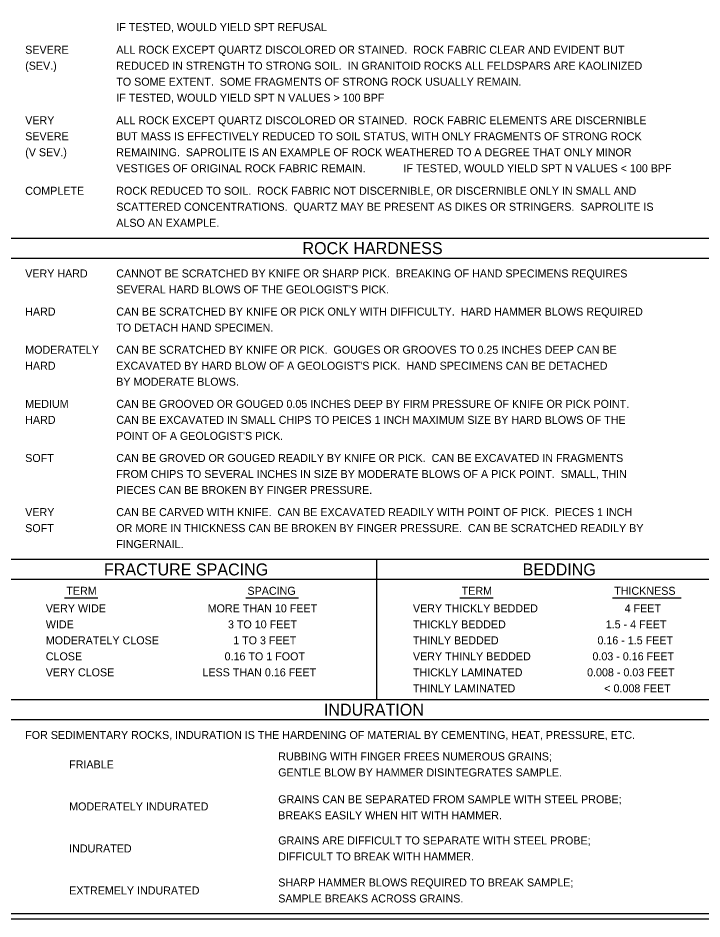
# Model space of a CAD drawing. Extents: x 265553 to 275568, y 168312 to 173522.
# Drawn here: x 267674.3 to 268044.8, y 170247.1 to 170735.3 of the extents above; entities that cross this region are included whole.
import ezdxf

# ---------------------------------------------------------------- set-up
doc = ezdxf.new("R2010")
doc.units = 0
doc.layers.add('Geotech Sheets and Borders Cell', color=7, linetype='Continuous')
doc.layers.add('Sheet Plot Border Inside CELL', color=7, linetype='Continuous')

msp = doc.modelspace()

# ---------------------------------------------------------------- linework, layer by layer
at = {"layer": 'Geotech Sheets and Borders Cell'}
for p, q in [((267670.42, 170616.07), (268066.96, 170616.07)), ((267670.42, 170605.22), (268066.96, 170605.22)), ((268420.42, 170441.94), (267670.42, 170441.94)), ((267868.69, 170365.94), (267868.69, 170441.94)), ((268066.96, 170431.1), (267670.42, 170431.1)), ((267699.57, 170421.19), (267717.57, 170421.19)), ((267797.7, 170421.19), (267826.25, 170421.19)), ((267913.75, 170421.19), (267931.75, 170421.19)), ((267996.37, 170421.19), (268033.61, 170421.19)), ((268066.96, 170365.94), (267670.42, 170365.94)), ((268066.96, 170355.1), (267670.42, 170355.1))]:
    msp.add_line(p, q, dxfattribs=at)
msp.add_lwpolyline([(266920.42, 171299.94), (268420.42, 171299.94), (268420.42, 170249.94), (266920.42, 170249.94)], close=True, dxfattribs=at)
at = {"layer": 'Sheet Plot Border Inside CELL'}
msp.add_lwpolyline([(266765.25, 170247.11), (268432.92, 170247.11), (268432.92, 171302.77), (266765.25, 171302.77)], close=True, dxfattribs=at)

# ---------------------------------------------------------------- texts
at = {"layer": 'Geotech Sheets and Borders Cell'}
for s, height, p in [('IF TESTED, WOULD YIELD SPT REFUSAL', 4.3381, (267727.56, 170728.22)), ('SEVERE', 4.338, (267678.23, 170715.99)), ('ALL ROCK EXCEPT QUARTZ DISCOLORED OR STAINED.  ROCK FABRIC CLEAR AND EVIDENT BUT ', 4.3381, (267727.56, 170715.99)), ('(SEV.)', 4.338, (267678.23, 170707.32)), ('REDUCED IN STRENGTH TO STRONG SOIL.  IN GRANITOID ROCKS ALL FELDSPARS ARE KAOLINIZED', 4.3381, (267727.56, 170707.32)), ('TO SOME EXTENT.  SOME FRAGMENTS OF STRONG ROCK USUALLY REMAIN.', 4.3381, (267727.56, 170698.65)), ('IF TESTED, WOULD YIELD SPT N VALUES > 100 BPF', 4.3381, (267727.56, 170689.99)), ('VERY', 4.338, (267678.23, 170677.77)), ('ALL ROCK EXCEPT QUARTZ DISCOLORED OR STAINED.  ROCK FABRIC ELEMENTS ARE DISCERNIBLE ', 4.3381, (267727.56, 170677.77)), ('SEVERE', 4.338, (267678.23, 170669.1)), ('BUT MASS IS EFFECTIVELY REDUCED TO SOIL STATUS, WITH ONLY FRAGMENTS OF STRONG ROCK ', 4.3381, (267727.56, 170669.1)), ('(V SEV.)', 4.338, (267678.23, 170660.43)), ('REMAINING.  SAPROLITE IS AN EXAMPLE OF ROCK WEATHERED TO A DEGREE THAT ONLY MINOR ', 4.3381, (267727.56, 170660.43)), ('VESTIGES OF ORIGINAL ROCK FABRIC REMAIN.   ', 4.3381, (267727.56, 170651.76)), ('IF TESTED, WOULD YIELD SPT N VALUES < 100 BPF', 4.3381, (267883.16, 170651.76)), ('COMPLETE', 4.338, (267678.23, 170639.55)), ('ROCK REDUCED TO SOIL.  ROCK FABRIC NOT DISCERNIBLE, OR DISCERNIBLE ONLY IN SMALL AND ', 4.3381, (267727.56, 170639.55)), ('SCATTERED CONCENTRATIONS.  QUARTZ MAY BE PRESENT AS DIKES OR STRINGERS.  SAPROLITE IS ', 4.3381, (267727.56, 170630.88)), ('ALSO AN EXAMPLE.', 4.3381, (267727.56, 170622.21)), ('ROCK HARDNESS', 6.507, (267828.44, 170607.39)), ('VERY HARD', 4.338, (267678.23, 170594.74)), ('CANNOT BE SCRATCHED BY KNIFE OR SHARP PICK.  BREAKING OF HAND SPECIMENS REQUIRES ', 4.3381, (267727.56, 170594.74)), ("SEVERAL HARD BLOWS OF THE GEOLOGIST'S PICK.", 4.3381, (267727.56, 170586.08)), ('HARD', 4.338, (267678.23, 170574.08)), ('CAN BE SCRATCHED BY KNIFE OR PICK ONLY WITH DIFFICULTY.  HARD HAMMER BLOWS REQUIRED ', 4.3381, (267727.56, 170574.08)), ('TO DETACH HAND SPECIMEN.', 4.3381, (267727.56, 170565.41)), ('MODERATELY', 4.338, (267678.23, 170553.41)), ('CAN BE SCRATCHED BY KNIFE OR PICK.  GOUGES OR GROOVES TO 0.25 INCHES DEEP CAN BE ', 4.3381, (267727.56, 170553.41)), ('HARD', 4.338, (267678.23, 170544.75)), ("EXCAVATED BY HARD BLOW OF A GEOLOGIST'S PICK.  HAND SPECIMENS CAN BE DETACHED ", 4.3381, (267727.56, 170544.75)), ('BY MODERATE BLOWS.', 4.3381, (267727.56, 170536.08)), ('MEDIUM', 4.338, (267678.23, 170524.08)), ('CAN BE GROOVED OR GOUGED 0.05 INCHES DEEP BY FIRM PRESSURE OF KNIFE OR PICK POINT.  ', 4.3381, (267727.56, 170524.08)), ('HARD', 4.338, (267678.23, 170515.41)), ('CAN BE EXCAVATED IN SMALL CHIPS TO PEICES 1 INCH MAXIMUM SIZE BY HARD BLOWS OF THE ', 4.3381, (267727.56, 170515.41)), ("POINT OF A GEOLOGIST'S PICK.", 4.3381, (267727.56, 170506.75)), ('SOFT', 4.338, (267678.23, 170494.75)), ('CAN BE GROVED OR GOUGED READILY BY KNIFE OR PICK.  CAN BE EXCAVATED IN FRAGMENTS ', 4.3381, (267727.56, 170494.75)), ('FROM CHIPS TO SEVERAL INCHES IN SIZE BY MODERATE BLOWS OF A PICK POINT.  SMALL, THIN ', 4.3381, (267727.56, 170486.08)), ('PIECES CAN BE BROKEN BY FINGER PRESSURE.', 4.3381, (267727.56, 170477.41)), ('VERY', 4.338, (267678.23, 170465.42)), ('CAN BE CARVED WITH KNIFE.  CAN BE EXCAVATED READILY WITH POINT OF PICK.  PIECES 1 INCH ', 4.3381, (267727.56, 170465.42)), ('SOFT', 4.338, (267678.23, 170456.75)), ('OR MORE IN THICKNESS CAN BE BROKEN BY FINGER PRESSURE.  CAN BE SCRATCHED READILY BY ', 4.3381, (267727.56, 170456.75)), ('FINGERNAIL.', 4.3381, (267727.56, 170448.08)), ('FRACTURE SPACING', 6.507, (267720.91, 170433.27)), ('BEDDING', 6.507, (267947.71, 170433.27)), ('TERM', 4.338, (267700.51, 170422.77)), ('SPACING', 4.338, (267798.64, 170422.77)), ('TERM', 4.338, (267914.69, 170422.77)), ('THICKNESS', 4.338, (267997.31, 170422.77)), ('VERY WIDE', 4.338, (267689.39, 170413.27)), ('MORE THAN 10 FEET', 4.3381, (267777.07, 170413.27)), ('VERY THICKLY BEDDED', 4.3381, (267888.28, 170413.27)), ('4 FEET', 4.338, (268002.97, 170413.27)), ('WIDE', 4.338, (267689.39, 170404.6)), ('3 TO 10 FEET', 4.3381, (267788.07, 170404.6)), ('THICKLY BEDDED', 4.3381, (267888.28, 170404.6)), ('1.5 - 4 FEET', 4.3381, (267992.72, 170404.6)), ('MODERATELY CLOSE', 4.3381, (267689.39, 170395.93)), ('1 TO 3 FEET', 4.3381, (267790.9, 170395.93)), ('THINLY BEDDED', 4.3381, (267888.28, 170395.93)), ('0.16 - 1.5 FEET', 4.3381, (267988.21, 170395.93)), ('CLOSE', 4.338, (267689.39, 170387.26)), ('0.16 TO 1 FOOT', 4.3381, (267786.25, 170387.26)), ('VERY THINLY BEDDED', 4.3381, (267888.28, 170387.26)), ('0.03 - 0.16 FEET', 4.3381, (267985.51, 170387.26)), ('VERY CLOSE', 4.338, (267689.39, 170378.6)), ('LESS THAN 0.16 FEET', 4.3381, (267774.23, 170378.6)), ('THICKLY LAMINATED', 4.3381, (267888.28, 170378.6)), ('0.008 - 0.03 FEET', 4.3381, (267982.61, 170378.6)), ('THINLY LAMINATED', 4.3381, (267888.28, 170369.93)), ('< 0.008 FEET', 4.3381, (267991.93, 170369.93)), ('INDURATION', 6.507, (267840.07, 170357.27)), ('FOR SEDIMENTARY ROCKS, INDURATION IS THE HARDENING OF MATERIAL BY CEMENTING, HEAT, PRESSURE, ETC.', 4.3381, (267678.23, 170344.65)), ('RUBBING WITH FINGER FREES NUMEROUS GRAINS;  ', 4.3381, (267815.3, 170333.03)), ('FRIABLE', 4.338, (267702.04, 170328.7)), ('GENTLE BLOW BY HAMMER DISINTEGRATES SAMPLE.', 4.3381, (267815.3, 170324.36)), ('GRAINS CAN BE SEPARATED FROM SAMPLE WITH STEEL PROBE;', 4.3381, (267815.3, 170309.8)), ('MODERATELY INDURATED', 4.3381, (267702.04, 170305.93)), ('BREAKS EASILY WHEN HIT WITH HAMMER.', 4.3381, (267815.3, 170301.13)), ('GRAINS ARE DIFFICULT TO SEPARATE WITH STEEL PROBE;  ', 4.3381, (267815.3, 170287.49)), ('INDURATED', 4.338, (267702.04, 170283.16)), ('DIFFICULT TO BREAK WITH HAMMER.', 4.3381, (267815.3, 170278.82)), ('SHARP HAMMER BLOWS REQUIRED TO BREAK SAMPLE;  ', 4.3381, (267815.3, 170264.72)), ('EXTREMELY INDURATED', 4.3381, (267702.04, 170260.39)), ('SAMPLE BREAKS ACROSS GRAINS.', 4.3381, (267815.3, 170256.05))]:
    msp.add_text(s, height=height, dxfattribs=at).set_placement(p)

doc.saveas('drawing.dxf')
